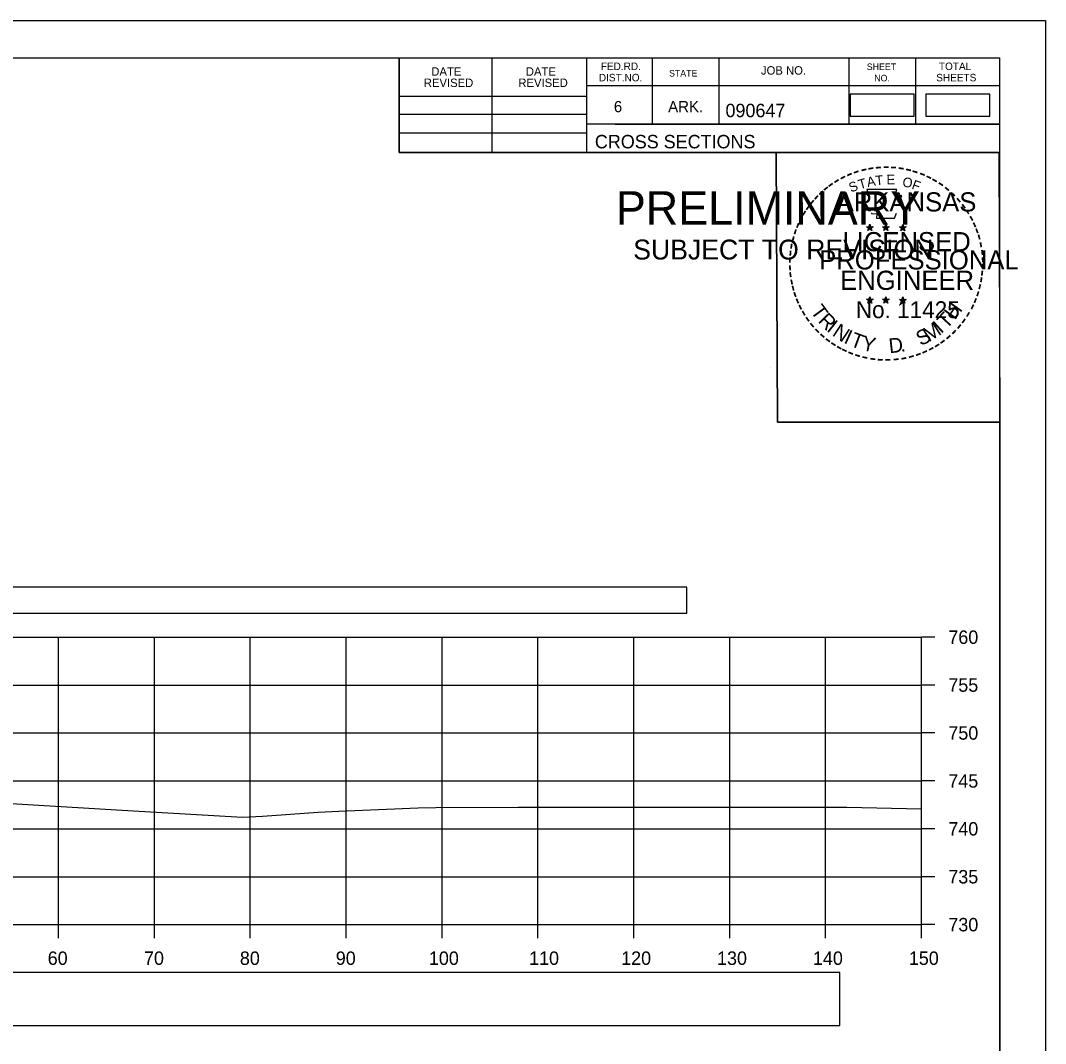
# Model space of a CAD drawing. Extents: x 1202951 to 1376887, y 378065 to 728038.
# Drawn here: x 1376640.7 to 1376747.6, y 379581.1 to 379687.9 of the extents above; entities that cross this region are included whole.
import ezdxf

# ---------------------------------------------------------------- set-up
doc = ezdxf.new("R2010")
doc.units = 0
for name, color, linetype in [('Default', 7, 'Continuous'), ('R_Alt Surface', 7, 'Continuous'), ('R_Axis', 7, 'Continuous'), ('R_Axis Annot', 7, 'Continuous'), ('R_Border', 7, 'Continuous'), ('R_Border PE', 7, 'Continuous'), ('R_Border Prem', 7, 'Continuous'), ('R_Exist Surface', 7, 'Continuous'), ('R_Grid', 7, 'Continuous'), ('R_No Plot', 7, 'Continuous')]:
    doc.layers.add(name, color=color, linetype=linetype)

msp = doc.modelspace()

# ---------------------------------------------------------------- linework, layer by layer
at = {"layer": 'Default'}
msp.add_lwpolyline([(1376735.11, 379677.87), (1376741.79, 379677.87), (1376741.79, 379680.18), (1376735.11, 379680.18)], close=True, dxfattribs=at)
at = {"layer": 'R_Alt Surface'}
for points in [[(1376727.24, 379677.87), (1376733.92, 379677.87), (1376733.92, 379680.18), (1376727.24, 379680.18)], [(1376434.67, 379626.01), (1376710.2, 379626.01), (1376710.2, 379628.71), (1376434.67, 379628.71)], [(1376615.43, 379582.98), (1376726.14, 379582.98), (1376726.14, 379588.51), (1376615.43, 379588.51)]]:
    msp.add_lwpolyline(points, close=True, dxfattribs=at)
at = {"layer": 'R_Axis'}
for p, q in [((1376734.67, 379593.51), (1376734.67, 379623.51)), ((1376736.07, 379623.51), (1376734.67, 379623.51)), ((1376736.07, 379618.51), (1376734.67, 379618.51)), ((1376736.07, 379613.51), (1376734.67, 379613.51)), ((1376736.07, 379608.51), (1376734.67, 379608.51)), ((1376736.07, 379603.51), (1376734.67, 379603.51)), ((1376736.07, 379598.51), (1376734.67, 379598.51)), ((1376434.67, 379593.51), (1376734.67, 379593.51)), ((1376644.67, 379592.11), (1376644.67, 379593.51)), ((1376654.67, 379592.11), (1376654.67, 379593.51)), ((1376664.67, 379592.11), (1376664.67, 379593.51)), ((1376674.67, 379592.11), (1376674.67, 379593.51)), ((1376684.67, 379592.11), (1376684.67, 379593.51)), ((1376694.67, 379592.11), (1376694.67, 379593.51)), ((1376704.67, 379592.11), (1376704.67, 379593.51)), ((1376714.67, 379592.11), (1376714.67, 379593.51)), ((1376724.67, 379592.11), (1376724.67, 379593.51)), ((1376734.67, 379592.11), (1376734.67, 379593.51)), ((1376736.07, 379593.51), (1376734.67, 379593.51))]:
    msp.add_line(p, q, dxfattribs=at)
at = {"layer": 'R_Border'}
for p, q in [((1376426.67, 379683.97), (1376742.85, 379683.97)), ((1376680.21, 379674.09), (1376680.21, 379683.97)), ((1376689.89, 379674.09), (1376689.89, 379683.97)), ((1376699.75, 379683.97), (1376699.75, 379674.09)), ((1376706.59, 379683.97), (1376706.59, 379677.03)), ((1376713.53, 379683.97), (1376713.53, 379677.03)), ((1376727.11, 379683.97), (1376727.11, 379677.03)), ((1376734.05, 379683.97), (1376734.05, 379677.03)), ((1376742.85, 379478.51), (1376742.85, 379683.97)), ((1376742.85, 379681.03), (1376699.75, 379681.03)), ((1376742.85, 379681.05), (1376742.85, 379681.05)), ((1376680.21, 379679.95), (1376699.75, 379679.95)), ((1376680.21, 379678.09), (1376699.75, 379678.09)), ((1376680.21, 379676.15), (1376699.75, 379676.15)), ((1376742.85, 379677.03), (1376699.75, 379677.03)), ((1376702.71, 379677.03), (1376742.85, 379677.03)), ((1376742.85, 379674.09), (1376680.21, 379674.09))]:
    msp.add_line(p, q, dxfattribs=at)
at = {"layer": 'R_Border PE'}
for p, q in [((1376729.28, 379666.6), (1376729.24, 379666.34)), ((1376729.28, 379666.23), (1376729.28, 379666.6)), ((1376729.28, 379666.6), (1376729.33, 379666.35)), ((1376730.95, 379666.6), (1376730.91, 379666.34)), ((1376730.95, 379666.23), (1376730.95, 379666.6)), ((1376730.95, 379666.6), (1376731, 379666.35)), ((1376732.72, 379666.58), (1376732.68, 379666.33)), ((1376732.72, 379666.22), (1376732.72, 379666.58)), ((1376732.72, 379666.58), (1376732.77, 379666.33)), ((1376728.94, 379666.34), (1376729.28, 379666.23)), ((1376728.94, 379666.34), (1376729.19, 379666.3)), ((1376728.94, 379666.34), (1376729.17, 379666.22)), ((1376729.07, 379665.93), (1376729.28, 379666.23)), ((1376729.07, 379665.93), (1376729.19, 379666.18)), ((1376729.07, 379665.93), (1376729.28, 379666.15)), ((1376729.63, 379666.34), (1376729.28, 379666.23)), ((1376729.5, 379665.93), (1376729.28, 379666.23)), ((1376729.5, 379665.93), (1376729.28, 379666.15)), ((1376729.63, 379666.34), (1376729.35, 379666.29)), ((1376729.5, 379665.93), (1376729.36, 379666.22)), ((1376729.63, 379666.34), (1376729.43, 379666.24)), ((1376730.61, 379666.34), (1376730.95, 379666.23)), ((1376730.61, 379666.34), (1376730.86, 379666.3)), ((1376730.61, 379666.34), (1376730.84, 379666.22)), ((1376730.74, 379665.93), (1376730.95, 379666.23)), ((1376730.74, 379665.93), (1376730.86, 379666.18)), ((1376730.74, 379665.93), (1376730.95, 379666.15)), ((1376731.3, 379666.34), (1376730.95, 379666.23)), ((1376731.17, 379665.93), (1376730.95, 379666.23)), ((1376731.17, 379665.93), (1376730.95, 379666.15)), ((1376731.3, 379666.34), (1376731.02, 379666.29)), ((1376731.17, 379665.93), (1376731.03, 379666.22)), ((1376731.3, 379666.34), (1376731.1, 379666.24)), ((1376732.37, 379666.33), (1376732.72, 379666.22)), ((1376732.37, 379666.33), (1376732.62, 379666.28)), ((1376732.37, 379666.33), (1376732.61, 379666.21)), ((1376732.5, 379665.92), (1376732.72, 379666.22)), ((1376732.5, 379665.92), (1376732.63, 379666.17)), ((1376732.5, 379665.92), (1376732.72, 379666.14)), ((1376733.07, 379666.33), (1376732.72, 379666.22)), ((1376732.93, 379665.92), (1376732.72, 379666.22)), ((1376732.93, 379665.92), (1376732.72, 379666.14)), ((1376733.07, 379666.33), (1376732.78, 379666.28)), ((1376732.93, 379665.92), (1376732.79, 379666.21)), ((1376733.07, 379666.33), (1376732.86, 379666.23)), ((1376728.93, 379658.77), (1376729.28, 379658.66)), ((1376728.93, 379658.77), (1376729.18, 379658.72)), ((1376728.93, 379658.77), (1376729.17, 379658.65)), ((1376729.06, 379658.36), (1376729.28, 379658.66)), ((1376729.06, 379658.36), (1376729.19, 379658.6)), ((1376729.06, 379658.36), (1376729.28, 379658.58)), ((1376729.28, 379659.02), (1376729.24, 379658.77)), ((1376729.28, 379658.66), (1376729.28, 379659.02)), ((1376729.28, 379659.02), (1376729.33, 379658.77)), ((1376729.63, 379658.77), (1376729.28, 379658.66)), ((1376729.49, 379658.36), (1376729.28, 379658.66)), ((1376729.49, 379658.36), (1376729.28, 379658.57)), ((1376729.63, 379658.77), (1376729.34, 379658.72)), ((1376729.49, 379658.36), (1376729.36, 379658.65)), ((1376729.63, 379658.77), (1376729.42, 379658.67)), ((1376730.6, 379658.77), (1376730.95, 379658.66)), ((1376730.6, 379658.77), (1376730.85, 379658.72)), ((1376730.6, 379658.77), (1376730.84, 379658.65)), ((1376730.73, 379658.36), (1376730.95, 379658.66)), ((1376730.73, 379658.36), (1376730.86, 379658.6)), ((1376730.73, 379658.36), (1376730.95, 379658.58)), ((1376730.95, 379659.02), (1376730.91, 379658.77)), ((1376730.95, 379658.66), (1376730.95, 379659.02)), ((1376730.95, 379659.02), (1376731, 379658.77)), ((1376731.3, 379658.77), (1376730.95, 379658.66)), ((1376731.16, 379658.36), (1376730.95, 379658.66)), ((1376731.16, 379658.36), (1376730.95, 379658.57)), ((1376731.3, 379658.77), (1376731.01, 379658.72)), ((1376731.16, 379658.36), (1376731.03, 379658.65)), ((1376731.3, 379658.77), (1376731.09, 379658.67)), ((1376732.37, 379658.76), (1376732.72, 379658.65)), ((1376732.37, 379658.76), (1376732.62, 379658.71)), ((1376732.37, 379658.76), (1376732.6, 379658.64)), ((1376732.5, 379658.35), (1376732.72, 379658.65)), ((1376732.5, 379658.35), (1376732.63, 379658.59)), ((1376732.5, 379658.35), (1376732.71, 379658.57)), ((1376732.72, 379659.01), (1376732.68, 379658.76)), ((1376732.93, 379658.35), (1376732.71, 379658.56)), ((1376732.72, 379658.65), (1376732.72, 379659.01)), ((1376732.72, 379659.01), (1376732.77, 379658.76)), ((1376733.06, 379658.76), (1376732.72, 379658.65)), ((1376732.93, 379658.35), (1376732.72, 379658.65)), ((1376733.06, 379658.76), (1376732.78, 379658.71)), ((1376732.93, 379658.35), (1376732.79, 379658.64)), ((1376733.06, 379658.76), (1376732.86, 379658.66))]:
    msp.add_line(p, q, dxfattribs=at)
for points in [[(1376728.98, 379670.22), (1376729.25, 379669.39)], [(1376732.49, 379669.3), (1376732.63, 379669.58), (1376731.94, 379669.56), (1376732.09, 379670.22), (1376728.98, 379670.22)], [(1376729.47, 379667.8), (1376729.47, 379667.71), (1376730.03, 379667.69), (1376729.98, 379667.22), (1376731.85, 379667.22), (1376732.05, 379667.75)], [(1376729.28, 379666.6), (1376729.5, 379665.93), (1376728.94, 379666.34), (1376729.63, 379666.34), (1376729.07, 379665.93), (1376729.28, 379666.6)], [(1376730.95, 379666.6), (1376731.17, 379665.93), (1376730.61, 379666.34), (1376731.3, 379666.34), (1376730.74, 379665.93), (1376730.95, 379666.6)], [(1376732.72, 379666.58), (1376732.93, 379665.92), (1376732.37, 379666.33), (1376733.07, 379666.33), (1376732.5, 379665.92), (1376732.72, 379666.58)], [(1376729.28, 379659.02), (1376729.49, 379658.36), (1376728.93, 379658.77), (1376729.63, 379658.77), (1376729.06, 379658.36), (1376729.28, 379659.02)], [(1376730.95, 379659.02), (1376731.16, 379658.36), (1376730.6, 379658.77), (1376731.3, 379658.77), (1376730.73, 379658.36), (1376730.95, 379659.02)], [(1376732.72, 379659.01), (1376732.93, 379658.35), (1376732.37, 379658.76), (1376733.06, 379658.76), (1376732.5, 379658.35), (1376732.72, 379659.01)]]:
    msp.add_lwpolyline(points, dxfattribs=at)
for centre, radius in [((1376729.28, 379666.23), 0.172), ((1376729.28, 379666.23), 0.145), ((1376729.28, 379666.23), 0.116), ((1376729.28, 379666.23), 0.0991), ((1376729.28, 379666.23), 0.0747), ((1376729.28, 379666.23), 0.0495), ((1376729.28, 379666.23), 0.0296), ((1376730.95, 379666.23), 0.172), ((1376730.95, 379666.23), 0.145), ((1376730.95, 379666.23), 0.116), ((1376730.95, 379666.23), 0.0991), ((1376730.95, 379666.23), 0.0747), ((1376730.95, 379666.23), 0.0495), ((1376730.95, 379666.23), 0.0296), ((1376732.72, 379666.22), 0.172), ((1376732.72, 379666.22), 0.145), ((1376732.72, 379666.22), 0.116), ((1376732.72, 379666.22), 0.0991), ((1376732.72, 379666.22), 0.0747), ((1376732.72, 379666.22), 0.0495), ((1376732.72, 379666.22), 0.0296), ((1376729.28, 379658.66), 0.172), ((1376729.28, 379658.66), 0.145), ((1376729.28, 379658.66), 0.116), ((1376729.28, 379658.66), 0.0991), ((1376729.28, 379658.66), 0.0747), ((1376729.28, 379658.66), 0.0495), ((1376729.28, 379658.66), 0.0296), ((1376730.95, 379658.66), 0.172), ((1376730.95, 379658.66), 0.145), ((1376730.95, 379658.66), 0.116), ((1376730.95, 379658.66), 0.0991), ((1376730.95, 379658.66), 0.0747), ((1376730.95, 379658.66), 0.0495), ((1376730.95, 379658.66), 0.0296), ((1376732.72, 379658.65), 0.172), ((1376732.72, 379658.65), 0.145), ((1376732.72, 379658.65), 0.116), ((1376732.72, 379658.65), 0.0991), ((1376732.72, 379658.65), 0.0747), ((1376732.72, 379658.65), 0.0495), ((1376732.72, 379658.65), 0.0296)]:
    msp.add_circle(centre, radius, dxfattribs=at)
at = {"layer": 'R_Exist Surface'}
msp.add_lwpolyline([(1376636.81, 379606.34), (1376651.3, 379605.44), (1376653.09, 379605.34), (1376663.86, 379604.73), (1376665.95, 379604.83), (1376671.75, 379605.25), (1376673.92, 379605.34), (1376682.18, 379605.7), (1376684.01, 379605.72), (1376692.6, 379605.78), (1376724.92, 379605.78), (1376726.88, 379605.77), (1376734.67, 379605.6)], dxfattribs=at)
at = {"layer": 'R_Grid'}
for p, q in [((1376434.67, 379623.51), (1376734.67, 379623.51)), ((1376644.67, 379593.51), (1376644.67, 379623.51)), ((1376654.67, 379593.51), (1376654.67, 379623.51)), ((1376664.67, 379593.51), (1376664.67, 379623.51)), ((1376674.67, 379593.51), (1376674.67, 379623.51)), ((1376684.67, 379593.51), (1376684.67, 379623.51)), ((1376694.67, 379593.51), (1376694.67, 379623.51)), ((1376704.67, 379593.51), (1376704.67, 379623.51)), ((1376714.67, 379593.51), (1376714.67, 379623.51)), ((1376724.67, 379593.51), (1376724.67, 379623.51)), ((1376734.67, 379593.51), (1376734.67, 379623.51)), ((1376434.67, 379618.51), (1376734.67, 379618.51)), ((1376434.67, 379613.51), (1376734.67, 379613.51)), ((1376434.67, 379608.51), (1376734.67, 379608.51)), ((1376434.67, 379603.51), (1376734.67, 379603.51)), ((1376434.67, 379598.51), (1376734.67, 379598.51)), ((1376434.67, 379593.51), (1376734.67, 379593.51))]:
    msp.add_line(p, q, dxfattribs=at)
at = {"layer": 'R_No Plot'}
for p, q in [((1376414.27, 379687.86), (1376747.6, 379687.86)), ((1376718.89, 379651.63), (1376718.89, 379651.63))]:
    msp.add_line(p, q, dxfattribs=at)
for points in [[(1376414.26, 379687.86), (1376747.6, 379687.86), (1376747.6, 379474.52), (1376414.26, 379474.52)], [(1376660.59, 379683.97), (1376680.21, 379683.97), (1376680.21, 379674.09), (1376696.32, 379674.09), (1376719.52, 379674.09), (1376719.64, 379645.93), (1376742.85, 379645.93), (1376742.85, 379478.51), (1376426.67, 379478.51), (1376426.67, 379683.97)], [(1376719.52, 379674.09), (1376742.73, 379674.09), (1376742.85, 379645.93), (1376719.64, 379645.93)]]:
    msp.add_lwpolyline(points, close=True, dxfattribs=at)

# ---------------------------------------------------------------- texts
at = {"layer": 'R_Axis Annot'}
for s, p in [('760', (1376737.47, 379622.81)), ('755', (1376737.47, 379617.81)), ('750', (1376737.47, 379612.81)), ('745', (1376737.47, 379607.81)), ('740', (1376737.47, 379602.81)), ('735', (1376737.47, 379597.81)), ('730', (1376737.47, 379592.81)), ('60', (1376643.55, 379589.31)), ('70', (1376653.59, 379589.31)), ('80', (1376663.59, 379589.31)), ('90', (1376673.59, 379589.31)), ('100', (1376683.3, 379589.31)), ('110', (1376693.75, 379589.31)), ('120', (1376703.35, 379589.31)), ('130', (1376713.35, 379589.31)), ('140', (1376723.35, 379589.31)), ('150', (1376733.35, 379589.31))]:
    msp.add_text(s, height=1.4, dxfattribs=at).set_placement(p)
at = {"layer": 'R_Border'}
for s, height, p in [('DATE', 0.879, (1376683.55, 379682.1)), ('DATE', 0.879, (1376693.41, 379682.1)), ('FED.RD.', 0.782, (1376701.23, 379682.69)), ('STATE', 0.684, (1376708.35, 379682.01)), ('JOB NO.', 0.879, (1376717.93, 379682.21)), ('SHEET', 0.684, (1376728.97, 379682.69)), ('TOTAL', 0.782, (1376736.49, 379682.69)), ('REVISED', 0.879, (1376682.77, 379680.92)), ('REVISED', 0.879, (1376692.63, 379680.92)), ('DIST.NO.', 0.782, (1376701.03, 379681.51)), ('NO.', 0.684, (1376729.75, 379681.51)), ('SHEETS', 0.782, (1376736.21, 379681.51)), ('6', 1.17, (1376702.59, 379678.29)), ('ARK.', 1.172, (1376708.25, 379678.29)), ('090647', 1.4, (1376714.23, 379677.77)), ('CROSS SECTIONS', 1.4, (1376700.61, 379674.52))]:
    msp.add_text(s, height=height, rotation=360, dxfattribs=at).set_placement(p)
at = {"layer": 'R_Border PE'}
for s, height, rotation, p in [('-', 1.6, 24.3072, (1376727.09, 379671.08)), ('-', 1.6, 19.1761, (1376727.72, 379671.35)), ('-', 1.6, 13.6301, (1376728.47, 379671.59)), ('-', 1.6, 10.2193, (1376729.15, 379671.75)), ('-', 1.6, 5.8968, (1376729.88, 379671.86)), ('-', 1.6, 0.1862, (1376730.65, 379671.93)), ('-', 1.6, 357.743, (1376731.38, 379671.92)), ('-', 1.6, 352.1617, (1376732.12, 379671.86)), ('-', 1.6, 347.2049, (1376732.84, 379671.75)), ('-', 1.6, 342.3362, (1376733.47, 379671.59)), ('-', 1.6, 337.8551, (1376734.21, 379671.37)), ('-', 1.6, 36.2317, (1376725.28, 379670)), ('-', 1.6, 34.0636, (1376725.86, 379670.39)), ('-', 1.6, 28.7918, (1376726.46, 379670.76)), ('S', 1, 21.594, (1376727.33, 379669.9)), ('T', 1, 16.4036, (1376728.25, 379670.23)), ('A', 1, 11.2132, (1376729.07, 379670.48)), ('T', 1, 6.0228, (1376729.92, 379670.65)), ('E', 1, 0.8323, (1376731.03, 379670.76)), ('O', 1, 350.4515, (1376732.63, 379670.55)), ('F', 1, 340.0707, (1376733.58, 379670.32)), ('-', 1.6, 334.1211, (1376734.84, 379671.1)), ('-', 1.6, 329.6409, (1376735.42, 379670.82)), ('-', 1.6, 325.8627, (1376736.06, 379670.46)), ('-', 1.6, 42.9622, (1376724.37, 379669.2)), ('-', 1.6, 38.9507, (1376724.81, 379669.62)), ('ARKANSAS', 2, 360, (1376725.83, 379667.93)), ('-', 1.6, 320.5297, (1376736.67, 379670.03)), ('-', 1.6, 315.5786, (1376737.27, 379669.54)), ('-', 1.6, 50.6142, (1376723.52, 379668.24)), ('-', 1.6, 48.423, (1376723.93, 379668.72)), ('-', 1.6, 309.8797, (1376737.84, 379668.99)), ('-', 1.6, 306.6522, (1376738.37, 379668.39)), ('-', 1.6, 58.0706, (1376722.78, 379667.14)), ('-', 1.6, 54.2325, (1376723.11, 379667.67)), ('-', 1.4, 303.6753, (1376738.85, 379667.82)), ('-', 1.6, 67.7743, (1376722.21, 379665.92)), ('-', 1.6, 62.8713, (1376722.47, 379666.53)), ('-', 1.6, 299.6684, (1376739.17, 379667.21)), ('-', 1.6, 294.6628, (1376739.49, 379666.6)), ('-', 1.6, 72.3945, (1376721.99, 379665.29)), ('LICENSED', 2, 360, (1376726.43, 379663.78)), ('DWB', 0.01, 360, (1376729.27, 379666.23)), ('DWB', 0.01, 360, (1376730.94, 379666.23)), ('DWB', 0.01, 360, (1376732.71, 379666.21)), ('-', 1.6, 290.5728, (1376739.75, 379666.03)), ('-', 1.6, 285.1233, (1376739.99, 379665.45)), ('-', 1.6, 81.2013, (1376721.66, 379663.86)), ('-', 1.6, 75.461, (1376721.8, 379664.57)), ('-', 1.6, 280.5493, (1376740.19, 379664.7)), ('-', 1.6, 85.1863, (1376721.59, 379663.17)), ('PROFESSIONAL', 2, 360, (1376724, 379661.88)), ('-', 1.6, 276.5962, (1376740.35, 379663.94)), ('-', 1.6, 94.1959, (1376721.6, 379661.74)), ('-', 1.6, 89.0622, (1376721.56, 379662.47)), ('-', 1.6, 274.3301, (1376740.41, 379663.21)), ('-', 1.6, 269.9407, (1376740.44, 379662.58)), ('-', 1.6, 98.9479, (1376721.67, 379661.08)), ('ENGINEER', 2, 360, (1376726.19, 379659.75)), ('-', 1.6, 263.5172, (1376740.42, 379661.92)), ('-', 1.6, 101.7149, (1376721.81, 379660.34)), ('-', 1.6, 105.4578, (1376721.97, 379659.75)), ('-', 1.6, 255.7626, (1376740.24, 379660.58)), ('-', 1.6, 260.9953, (1376740.35, 379661.26)), ('-', 1.6, 109.0874, (1376722.18, 379659.12)), ('-', 1.6, 252.8681, (1376740.06, 379659.86)), ('-', 1.6, 114.0643, (1376722.44, 379658.52)), ('-', 1.6, 115.7289, (1376722.74, 379657.9)), ('T', 1.54, 306.0406, (1376723.04, 379657.5)), ('No. 11425', 1.757, 360, (1376727.82, 379656.8)), ('DWB', 0.01, 360, (1376729.27, 379658.65)), ('DWB', 0.01, 360, (1376730.94, 379658.65)), ('DWB', 0.01, 360, (1376732.7, 379658.64)), ('H', 1.54, 54.6088, (1376738.16, 379656.53)), ('-', 1.6, 244.6197, (1376739.58, 379658.56)), ('-', 1.6, 247.8887, (1376739.84, 379659.19)), ('-', 1.6, 120.4471, (1376723.1, 379657.32)), ('-', 1.6, 125.8934, (1376723.5, 379656.76)), ('R', 1.54, 314.005, (1376723.8, 379656.45)), ('T', 1.54, 46.6444, (1376737.27, 379655.59)), ('-', 1.6, 239.0712, (1376739.18, 379657.81)), ('-', 1.6, 130.7181, (1376723.96, 379656.2)), ('I', 1.54, 321.9694, (1376724.7, 379655.52)), ('N', 1.54, 326.5002, (1376725.27, 379655.04)), ('M', 1.54, 32.6563, (1376735.43, 379654.26)), ('I', 1.54, 42.1136, (1376736.71, 379655.11)), ('-', 1.6, 231.2538, (1376738.35, 379656.59)), ('-', 1.6, 233.8452, (1376738.78, 379657.16)), ('-', 1.6, 134.2238, (1376724.48, 379655.66)), ('-', 1.6, 138.9338, (1376725.01, 379655.2)), ('I', 1.54, 335.3603, (1376726.48, 379654.26)), ('T', 1.54, 339.8912, (1376727.14, 379653.93)), ('Y', 1.54, 347.8556, (1376728.36, 379653.49)), ('D', 1.54, 6.3969, (1376731.34, 379653.13)), ('S', 1.54, 26.9312, (1376734.59, 379653.86)), ('-', 1.6, 221.0851, (1376737.35, 379655.52)), ('-', 1.6, 225.7653, (1376737.87, 379656.03)), ('-', 1.6, 144.6463, (1376725.56, 379654.79)), ('-', 1.6, 148.0898, (1376726.12, 379654.42)), ('-', 1.6, 151.5704, (1376726.7, 379654.09)), ('-', 1.6, 207.3568, (1376735.71, 379654.31)), ('-', 1.6, 212.2491, (1376736.27, 379654.66)), ('-', 1.6, 215.7363, (1376736.8, 379655.05)), ('-', 1.6, 154.6002, (1376727.22, 379653.85)), ('-', 1.6, 158.5612, (1376727.85, 379653.59)), ('-', 1.6, 162.7983, (1376728.53, 379653.38)), ('-', 1.6, 167.5555, (1376729.25, 379653.22)), ('-', 1.6, 173.1155, (1376730.02, 379653.11)), ('-', 1.6, 185.8167, (1376732.32, 379653.15)), ('-', 1.6, 191.2858, (1376733.06, 379653.28)), ('.', 1.54, 13.7642, (1376732.53, 379653.25)), ('-', 1.6, 195.4743, (1376733.79, 379653.48)), ('-', 1.6, 200.7184, (1376734.46, 379653.72)), ('-', 1.6, 204.2516, (1376735.08, 379653.99)), ('-', 1.6, 176.5183, (1376730.77, 379653.05)), ('-', 1.6, 181.5918, (1376731.51, 379653.07))]:
    msp.add_text(s, height=height, rotation=rotation, dxfattribs=at).set_placement(p)
at = {"layer": 'R_Border Prem'}
for s, height, p in [('PRELIMINARY', 3.5, (1376702.8, 379666.55)), ('DWB', 0.01, (1376703.55, 379668.4)), ('SUBJECT TO REVISION', 2.0751, (1376704.61, 379662.92))]:
    msp.add_text(s, height=height, rotation=360, dxfattribs=at).set_placement(p)

doc.saveas('drawing.dxf')
